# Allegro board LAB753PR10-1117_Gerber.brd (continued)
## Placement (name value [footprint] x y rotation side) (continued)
CV34  10U_0603_6.3V6M~D  [C_0603]  147.53 136.59 0 bottom
CV35  0.1U_0402_16V7K~D  [C_0402]  146.53 136.93 180 bottom
CV37  0.1U_0402_10V7K  [C_0402]  113.93 143.89 90 top
CV38  0.1U_0402_10V7K  [C_0402]  113.01 143.89 90 top
CV39  0.1U_0402_10V7K  [C_0402]  112.08 144.64 90 top
CV41  0.1U_0402_10V7K  [C_0402]  111.14 144.64 90 top
CV42  0.1U_0402_10V7K  [C_0402]  110.26 143.8 90 top
CV43  0.1U_0402_10V7K  [C_0402]  109.35 143.8 90 top
CV44  0.1U_0402_10V7K  [C_0402]  108.47 143.82 90 top
CV45  0.1U_0402_10V7K  [C_0402]  107.52 143.83 90 top
CV47  0.1U_0402_16V7K  [C_0402]  135.22 135.61 270 bottom
CV54  0.1U_0402_25V6K~D  [C_0402]  138.09 82.31 90 bottom
CV57  0.22U_0402_10V6K  [C_0402]  152.59 82.94 0 top
CV58  0.22U_0402_10V6K  [C_0402]  152.9 85.87 0 top
CV59  0.22U_0402_10V6K  [C_0402]  154.93 84.27 0 top
CV60  0.22U_0402_10V6K  [C_0402]  154.93 85.2 0 top
CV61  0.22U_0402_10V6K  [C_0402]  154.93 88.01 0 top
CV62  0.22U_0402_10V6K  [C_0402]  152.59 83.87 0 top
CV63  0.22U_0402_10V6K  [C_0402]  152.9 86.8 0 top
CV64  0.22U_0402_10V6K  [C_0402]  154.93 87.11 0 top
CV65  0.22U_0402_10V6K  [C_0402]  152.59 91.13 0 top
CV66  0.22U_0402_10V6K  [C_0402]  154.93 93.6 0 top
CV67  0.22U_0402_10V6K  [C_0402]  153.09 89.47 0 top
CV68  0.22U_0402_10V6K  [C_0402]  154.93 90.79 0 top
CV69  0.22U_0402_10V6K  [C_0402]  154.93 89.86 0 top
CV70  0.22U_0402_10V6K  [C_0402]  152.59 92.06 0 top
CV71  0.22U_0402_10V6K  [C_0402]  153.09 88.49 0 top
CV72  0.22U_0402_10V6K  [C_0402]  154.93 92.67 0 top
CV73  22P_0402_50V8J  [C_0402]  170.52 64.31 180 bottom
CV74  22P_0402_50V8J  [C_0402]  167.76 64.31 0 bottom
CV75  0.1U_0402_10V7K  [C_0402]  190.01 83.93 180 top
CV76  0.1U_0402_10V7K  [C_0402]  170.89 88.2 270 top
CV80  0.1U_0402_10V7K  [C_0402]  170.76 89.06 90 top
CV81  10U_0603_6.3V6M  [C_0603]  211.71 103.91 90 top
CV82  4.7U_0603_6.3V6K  [C_0603]  229.53 77.24 0 top
CV83  4.7U_0603_6.3V6K  [C_0603]  229.53 77.24 0 bottom
CV84  4.7U_0603_6.3V6K  [C_0603]  176.41 100.27 90 top
CV85  22U_0805_6.3V6M  [C_0805]  229.59 86.86 0 top
CV86  22U_0805_6.3V6M  [C_0805]  229.61 86.86 0 bottom
CV87  22U_0805_6.3V6M  [C_0805]  229.58 70.07 0 bottom
CV88  22U_0805_6.3V6M  [C_0805]  229.58 70.07 0 top
CV89  10U_0603_6.3V6M  [C_0603]  213.11 103.91 90 top
CV90  10U_0603_6.3V6M  [C_0603]  215.9 103.91 90 top
CV91  4.7U_0603_6.3V6K  [C_0603]  178.82 98.45 90 top
CV92  4.7U_0603_6.3V6K  [C_0603]  188.39 74.29 270 top
CV93  10U_0603_6.3V6M  [C_0603]  230.95 72.89 180 top
CV94  10U_0603_6.3V6M  [C_0603]  158.31 93.52 90 bottom
CV95  4.7U_0603_6.3V6K  [C_0603]  158.32 96.98 90 bottom
CV96  1U_0402_6.3V6K  [C_0402]  169.23 88.47 90 top
CV97  22U_0805_6.3V6M  [C_0805]  154.38 96.92 90 bottom
CV98  10U_0603_6.3V6M  [C_0603]  157.11 93.52 90 bottom
CV99  10U_0603_6.3V6M  [C_0603]  155.9 93.52 90 bottom
CV100  1U_0402_6.3V6K  [C_0402]  190.01 83.04 180 top
CV101  1U_0402_6.3V6K  [C_0402]  189.17 79.47 90 top
CV102  1U_0402_6.3V6K  [C_0402]  190.01 84.82 180 top
CV103  1U_0402_6.3V6K  [C_0402]  191.49 92.6 0 top
CV104  1U_0402_6.3V6K  [C_0402]  189.17 90.9 90 top
CV105  1U_0402_6.3V6K  [C_0402]  190.77 80.63 0 top
CV106  1U_0402_6.3V6K  [C_0402]  188.01 96.69 270 top
CV107  1U_0402_6.3V6K  [C_0402]  185.39 96.77 270 top
CV108  22U_0805_6.3V6M  [C_0805]  151.39 102.2 270 top
CV109  0.1U_0402_10V7K  [C_0402]  183.64 96.76 270 top
CV110  4.7U_0603_6.3V6K  [C_0603]  190.46 76.23 315 top
CV111  10U_0603_6.3V6M  [C_0603]  154.43 94.79 0 top
CV112  1U_0402_6.3V6K  [C_0402]  181.03 96.78 270 top
CV113  1U_0402_6.3V6K  [C_0402]  176.28 96.77 270 top
CV114  1U_0402_6.3V6K  [C_0402]  169.29 93.49 90 top
CV115  22U_0805_6.3V6M  [C_0805]  152.6 96.92 90 bottom
CV116  22U_0805_6.3V6M  [C_0805]  152.6 94.81 270 bottom
CV117  1U_0402_6.3V6K  [C_0402]  168.86 85.56 180 top
CV118  1U_0402_6.3V6K  [C_0402]  169.29 91.2 90 top
CV119  4.7U_0603_6.3V6K  [C_0603]  155.83 96.06 180 top
CV120  22U_0805_6.3V6M  [C_0805]  154.38 94.81 270 bottom
CV121  4.7U_0603_6.3V6K  [C_0603]  167.96 80.85 90 top
CV122  0.1U_0402_10V7K  [C_0402]  170.75 91.76 270 top
CV123  1U_0402_6.3V6K  [C_0402]  169.88 90.26 180 top
CV124  1U_0603_10V6K  [C_0603]  167.83 95.59 0 top
CV125  4.7U_0805_25V6-K  [C_0805]  156.15 96.92 90 bottom
CV126  0.1U_0402_10V7K  [C_0402]  170.02 87.25 270 top
CV127  0.1U_0402_10V7K  [C_0402]  169.5 79.28 0 top
CV128  0.1U_0402_10V7K  [C_0402]  169.29 78.23 0 top
CV129  1U_0603_10V6K  [C_0603]  168.76 76.76 0 top
CV130  4.7U_0805_25V6-K  [C_0805]  171.31 75.07 180 top
CV131  0.1U_0402_10V7K  [C_0402]  181.89 96.78 270 top
CV132  0.1U_0402_10V7K  [C_0402]  169.01 80.71 0 top
CV133  1U_0603_10V6K  [C_0603]  155.79 78.63 180 bottom
CV134  4.7U_0805_25V6-K  [C_0805]  155.92 80.16 180 bottom
CV135  1U_0402_6.3V6K  [C_0402]  189.17 76.81 90 top
CV136  1U_0402_6.3V6K  [C_0402]  174.13 99.05 90 top
CV137  22U_0805_6.3V6M  [C_0805]  191.54 86.16 0 top
CV138  22U_0805_6.3V6M  [C_0805]  190.13 95.11 90 top
CV139  10U_0603_6.3V6M  [C_0603]  230.89 88.76 180 top
CV140  10U_0603_6.3V6M  [C_0603]  210.31 103.91 90 top
CV141  1U_0402_6.3V6K  [C_0402]  182.77 96.78 270 top
CV142  1U_0402_6.3V6K  [C_0402]  185.31 77.64 180 top
CV143  4.7U_0603_6.3V6K  [C_0603]  186 75.04 270 top
CV144  4.7U_0603_6.3V6K  [C_0603]  183.62 97.84 90 top
CV145  4.7U_0603_6.3V6K  [C_0603]  214.51 105.31 270 top
CV146  4.7U_0603_6.3V6K  [C_0603]  229.49 88.76 0 bottom
CV147  0.1U_0402_10V7K  [C_0402]  180 76.76 90 top
CV148  22U_0805_6.3V6M  [C_0805]  156.73 64.99 90 bottom
CV149  0.1U_0402_10V7K  [C_0402]  171.35 76.85 0 top
CV150  10U_0603_6.3V6M  [C_0603]  180.31 91.05 0 top
CV151  10U_0603_6.3V6M  [C_0603]  180.3 83.44 0 top
CV152  10U_0603_6.3V6M  [C_0603]  180.19 81.49 0 top
CV153  0.1U_0402_10V6K  [C_0402]  162.45 119.68 180 bottom
CV154  0.1U_0402_10V6K  [C_0402]  161.71 132.91 180 top
CV155  0.1U_0402_10V6K  [C_0402]  184.03 130.63 90 bottom
CV156  0.1U_0402_10V6K  [C_0402]  180.47 126.65 90 top
CV157  10U_0603_6.3V6M  [C_0603]  175.65 84.18 180 top
CV158  10U_0603_6.3V6M  [C_0603]  176.49 81.24 0 top
CV159  4.7U_0603_6.3V6K  [C_0603]  187.52 93.44 270 top
CV160  0.1U_0402_10V6K  [C_0402]  162.46 118.8 180 bottom
CV161  0.1U_0402_10V6K  [C_0402]  179.59 124.81 90 bottom
CV162  1U_0402_6.3V4Z  [C_0402]  179.59 115.5 270 bottom
CV163  1U_0402_6.3V4Z  [C_0402]  179.59 117.28 270 bottom
CV164  0.1U_0402_10V6K  [C_0402]  162.46 117.92 180 bottom
CV165  0.1U_0402_10V6K  [C_0402]  179.59 126.65 90 bottom
CV166  1U_0402_6.3V4Z  [C_0402]  162.45 123.23 180 bottom
CV167  0.1U_0402_10V6K  [C_0402]  165.69 129.69 90 top
CV168  0.1U_0402_10V6K  [C_0402]  162.32 124.36 180 top
CV169  1U_0402_6.3V4Z  [C_0402]  166.58 131.49 180 top
CV170  1U_0402_6.3V4Z  [C_0402]  162.32 123.48 180 top
CV171  0.1U_0402_10V6K  [C_0402]  176.72 130.7 90 top
CV172  0.1U_0402_10V6K  [C_0402]  175.83 130.7 90 top
CV173  1U_0402_6.3V4Z  [C_0402]  179.59 124.81 90 top
CV174  0.1U_0402_10V6K  [C_0402]  180.47 115.5 270 bottom
CV175  0.1U_0402_10V6K  [C_0402]  180.47 117.28 270 bottom
CV178  820P_0402_25V7  [C_0402]  229.53 95.51 270 top
CV179  820P_0402_25V7  [C_0402]  215.13 103.98 0 bottom
CV180  0.1U_0402_10V6K  [C_0402]  215.71 65.79 270 top
CV181  0.1U_0402_10V6K  [C_0402]  224.87 84.16 180 top
CV182  1U_0402_6.3V4Z  [C_0402]  227.52 83.3 0 top
CV184  0.1U_0402_10V6K  [C_0402]  222 66.16 270 top
CV185  0.1U_0402_10V6K  [C_0402]  229.73 80.65 0 top
CV186  1U_0402_6.3V4Z  [C_0402]  214.11 83.28 0 top
CV187  1U_0402_6.3V4Z  [C_0402]  226.65 83.3 180 top
CV188  0.1U_0402_10V6K  [C_0402]  222.96 66.23 270 bottom
CV189  0.1U_0402_10V6K  [C_0402]  229.73 79.63 0 top
CV190  1U_0402_6.3V4Z  [C_0402]  229.73 78.62 0 top
CV191  1U_0402_6.3V4Z  [C_0402]  229.73 80.65 0 bottom
CV192  0.1U_0402_10V6K  [C_0402]  229.35 84.15 0 bottom
CV193  0.1U_0402_10V6K  [C_0402]  229.73 79.63 0 bottom
CV194  1U_0402_6.3V4Z  [C_0402]  229.73 78.62 0 bottom
CV195  0.1U_0402_16V4Z~D  [C_0402]  153.09 80.61 270 bottom
CV198  1U_0402_6.3V4Z  [C_0402]  180.47 122.87 270 bottom
CV199  1U_0402_6.3V4Z  [C_0402]  180.47 124.81 90 bottom
CV200  0.1U_0402_10V6K  [C_0402]  163.45 128.49 90 bottom
CV201  0.1U_0402_10V6K  [C_0402]  179.59 126.65 90 top
CV202  0.1U_0402_10V6K  [C_0402]  180.47 126.65 90 bottom
CV203  0.1U_0402_10V7K  [C_0402]  190.69 90.34 0 top
CV204  0.1U_0402_10V7K  [C_0402]  190.08 78.57 180 top
CV205  0.1U_0402_10V7K  [C_0402]  189.17 81.25 90 top
CV206  0.1U_0402_10V7K  [C_0402]  189.17 90.04 270 top
CV207  0.1U_0402_10V7K  [C_0402]  190.01 85.71 180 top
CV208  0.1U_0402_10V7K  [C_0402]  173.3 96.77 270 top
CV209  0.1U_0402_10V7K  [C_0402]  186.19 76.74 90 top
CV210  0.1U_0402_10V6K  [C_0402]  197.61 114.16 0 bottom
CV211  0.1U_0402_10V6K  [C_0402]  197.61 115.11 0 bottom
CV212  0.1U_0402_10V7K  [C_0402]  153.74 73.5 90 bottom
CV213  1U_0402_6.3V4Z  [C_0402]  197.61 116.06 0 bottom
CV214  0.1U_0402_10V6K  [C_0402]  184.13 130.64 90 top
CV215  0.1U_0402_10V7K  [C_0402]  187.07 77.64 0 top
CV216  0.1U_0402_10V6K  [C_0402]  162.46 116.14 180 bottom
CV217  10U_0603_6.3V6M  [C_0603]  178.22 129.95 90 bottom
CV218  10U_0603_6.3V6M  [C_0603]  162.97 124.32 180 bottom
CV219  0.1U_0402_10V6K  [C_0402]  162.45 122.33 180 bottom
CV220  1U_0402_6.3V4Z  [C_0402]  162.46 117.03 180 bottom
CV221  0.1U_0402_10V6K  [C_0402]  171.62 130.61 90 bottom
CV222  0.1U_0402_10V6K  [C_0402]  164.73 129.68 0 bottom
CV223  0.1U_0402_10V6K  [C_0402]  174.51 130.7 90 top
CV224  10U_0603_6.3V6M  [C_0603]  180.57 130.04 90 top
CV225  10U_0603_6.3V6M  [C_0603]  173.23 130.57 90 top
CV226  0.1U_0402_10V6K  [C_0402]  179.63 113.69 0 top
CV227  1U_0402_6.3V4Z  [C_0402]  179.59 117.28 270 top
CV228  0.1U_0402_10V6K  [C_0402]  179.59 115.5 270 top
CV229  0.1U_0402_10V6K  [C_0402]  163.5 128.11 180 top
CV230  0.1U_0402_10V6K  [C_0402]  190.69 130.63 90 bottom
CV231  10U_0603_6.3V6M  [C_0603]  197.68 127.05 0 bottom
CV232  10U_0603_6.3V6M  [C_0603]  197.68 128.32 0 bottom
CV233  0.1U_0402_10V6K  [C_0402]  189.8 130.63 90 bottom
CV234  1U_0402_6.3V4Z  [C_0402]  197.61 124.19 0 bottom
CV235  0.1U_0402_10V6K  [C_0402]  197.61 125.97 0 bottom
CV236  0.1U_0402_10V6K  [C_0402]  197.61 125.08 0 bottom
CV237  0.1U_0402_10V6K  [C_0402]  179.47 130.7 90 top
CV238  10U_0603_6.3V6M  [C_0603]  195.37 130.72 90 top
CV239  10U_0603_6.3V6M  [C_0603]  196.6 130.71 90 top
CV240  0.1U_0402_10V6K  [C_0402]  182.35 130.64 90 top
CV241  0.1U_0402_10V6K  [C_0402]  183.23 130.64 90 top
CV242  1U_0402_6.3V4Z  [C_0402]  201.6 128.12 0 top
CV243  1U_0402_6.3V4Z  [C_0402]  185.17 130.63 90 top
CV244  0.1U_0402_10V6K  [C_0402]  178.55 130.7 90 top
CV245  0.1U_0402_10V6K  [C_0402]  177.66 130.7 90 top
CV246  0.1U_0402_10V6K  [C_0402]  180.47 115.5 270 top
CV247  1U_0402_6.3V4Z  [C_0402]  180.47 117.28 270 top
CV248  1U_0402_6.3V4Z  [C_0402]  180.47 124.81 90 top
CV249  0.1U_0402_10V6K  [C_0402]  186.12 130.63 90 top
CV250  0.1U_0402_10V6K  [C_0402]  180.47 122.6 270 top
CV252  0.1U_0402_10V6K  [C_0402]  227.52 84.18 0 top
CV253  10U_0603_6.3V6M  [C_0603]  228.29 101.46 90 top
CV254  0.1U_0402_10V6K  [C_0402]  226.65 84.18 180 top
CV255  0.1U_0402_10V6K  [C_0402]  213.24 83.33 90 top
CV256  0.1U_0402_10V6K  [C_0402]  224.8 101.44 90 top
CV257  10U_0603_6.3V6M  [C_0603]  226.96 101.46 90 top
CV258  1U_0402_6.3V4Z  [C_0402]  225.69 101.44 90 top
CV259  1U_0402_6.3V4Z  [C_0402]  229.55 99.1 270 top
CV260  0.1U_0402_10V6K  [C_0402]  223.91 101.44 90 top
CV261  0.1U_0402_10V6K  [C_0402]  223.02 101.44 90 top
CV262  0.1U_0402_10V6K  [C_0402]  222.13 101.44 90 top
CV263  1U_0402_6.3V4Z  [C_0402]  221.18 101.44 90 top
CV264  1U_0402_6.3V4Z  [C_0402]  214.7 101.63 90 top
CV265  0.1U_0402_10V6K  [C_0402]  217.5 101.63 90 top
CV266  0.1U_0402_10V6K  [C_0402]  216.54 101.63 90 top
CV267  0.1U_0402_10V6K  [C_0402]  223.96 84.18 0 bottom
CV268  10U_0603_6.3V6M  [C_0603]  222.95 83.47 180 bottom
CV269  10U_0603_6.3V6M  [C_0603]  229.49 90.05 0 bottom
CV270  0.1U_0402_10V6K  [C_0402]  226.65 84.18 180 bottom
CV271  0.1U_0402_10V6K  [C_0402]  227.52 84.18 0 bottom
CV272  0.1U_0402_10V6K  [C_0402]  214.12 83.28 0 bottom
CV273  0.1U_0402_10V6K  [C_0402]  224.8 101.44 90 bottom
CV274  1U_0402_6.3V4Z  [C_0402]  214.12 84.18 0 bottom
CV275  1U_0402_6.3V4Z  [C_0402]  229.56 99.09 270 bottom
CV276  0.1U_0402_10V6K  [C_0402]  229.56 100.87 270 bottom
CV277  0.1U_0402_10V6K  [C_0402]  225.69 101.44 90 bottom
CV278  0.1U_0402_10V6K  [C_0402]  211.08 101.6 90 bottom
CV279  1U_0402_6.3V4Z  [C_0402]  212.03 101.6 90 bottom
CV280  1U_0402_6.3V4Z  [C_0402]  223.91 101.44 90 bottom
CV281  0.1U_0402_10V6K  [C_0402]  226.57 101.42 90 bottom
CV282  0.1U_0402_10V6K  [C_0402]  210.19 101.61 90 bottom
CV283  0.1U_0402_10V6K  [C_0402]  215.59 101.63 90 top
CV284  0.1U_0402_10V6K  [C_0402]  229.91 68.38 0 top
CV285  10U_0603_6.3V6M  [C_0603]  229.55 72.89 0 bottom
CV286  10U_0603_6.3V6M  [C_0603]  229.55 74.44 0 top
CV287  0.1U_0402_10V6K  [C_0402]  222.96 66.16 270 top
CV288  1U_0402_6.3V4Z  [C_0402]  214.61 65.8 270 top
CV289  0.1U_0402_10V6K  [C_0402]  229.91 67.36 0 top
CV290  0.1U_0402_10V6K  [C_0402]  215.89 83.3 0 top
CV291  0.1U_0402_10V6K  [C_0402]  217.43 65.87 270 top
CV292  10U_0603_6.3V6M  [C_0603]  229.53 75.81 0 top
CV293  10U_0603_6.3V6M  [C_0603]  229.55 71.59 0 top
CV294  0.1U_0402_10V6K  [C_0402]  227.52 83.3 0 bottom
CV295  0.1U_0402_10V6K  [C_0402]  223.96 83.3 0 bottom
CV296  1U_0402_6.3V4Z  [C_0402]  226.65 83.3 180 bottom
CV297  0.1U_0402_10V6K  [C_0402]  215.89 83.3 0 bottom
CV298  0.1U_0402_10V6K  [C_0402]  222 66.23 270 bottom
CV299  820P_0402_25V7  [C_0402]  229.53 95.5 270 bottom
CV300  820P_0402_25V7  [C_0402]  216.53 101.61 0 bottom
CV301  820P_0402_25V7  [C_0402]  179.58 122.85 270 bottom
CV302  820P_0402_25V7  [C_0402]  169.41 130.6 0 top
CV303  820P_0402_25V7  [C_0402]  161.56 121.46 270 bottom
CV304  820P_0402_25V7  [C_0402]  173.03 130.6 0 bottom
CV305  820P_0402_25V7  [C_0402]  197.68 127.67 90 top
CV306  820P_0402_25V7  [C_0402]  192.55 130.69 180 bottom
CV307  820P_0402_25V7  [C_0402]  197.61 123.24 0 bottom
CV308  820P_0402_25V7  [C_0402]  192.55 130.68 180 top
CV309  820P_0402_25V7  [C_0402]  219.07 66.21 0 bottom
CV310  820P_0402_25V7  [C_0402]  219.07 64.44 0 bottom
CV311  820P_0402_25V7  [C_0402]  220.1 66.16 270 top
CV312  820P_0402_25V7  [C_0402]  229.47 75.97 0 bottom
CV313  0.1U_0402_10V6K  [C_0402]  229.91 68.38 0 bottom
CV314  0.1U_0402_10V6K  [C_0402]  229.91 67.36 0 bottom
CV315  0.1U_0402_10V6K  [C_0402]  214.11 84.16 0 top
CV317  4.7U_0603_6.3V6K  [C_0603]  177.48 93.18 90 top
CV318  4.7U_0603_6.3V6K  [C_0603]  178.7 86.24 180 top
CV319  4.7U_0603_6.3V6K  [C_0603]  172.49 90.39 270 top
CV320  4.7U_0603_6.3V6K  [C_0603]  187.52 87.53 270 top
CV321  4.7U_0603_6.3V6K  [C_0603]  183.44 89.37 270 top
CV322  4.7U_0603_6.3V6K  [C_0603]  184.67 86.31 180 top
CV323  4.7U_0603_6.3V6K  [C_0603]  172.49 80.04 90 top
CV324  4.7U_0603_6.3V6K  [C_0603]  187.52 89.12 90 top
CV325  4.7U_0603_6.3V6K  [C_0603]  170.75 82.01 180 top
CV326  4.7U_0603_6.3V6K  [C_0603]  181.69 85.16 180 top
CV327  4.7U_0603_6.3V6K  [C_0603]  178.76 88.15 180 top
CV328  4.7U_0603_6.3V6K  [C_0603]  187.52 83.02 90 top
CV329  4.7U_0603_6.3V6K  [C_0603]  179.54 68.12 270 top
CV330  4.7U_0603_6.3V6K  [C_0603]  181.69 87.26 180 top
CV331  4.7U_0603_6.3V6K  [C_0603]  172.49 84.49 270 top
CV332  4.7U_0603_6.3V6K  [C_0603]  187.52 81.37 270 top
CV333  4.7U_0603_6.3V6K  [C_0603]  171.41 71.07 180 top
CV334  4.7U_0603_6.3V6K  [C_0603]  181.71 89.24 180 top
CV335  4.7U_0603_6.3V6K  [C_0603]  172.49 86.08 90 top
CV338  47U_0805_6.3V6M~D  [C_0805]  229.62 82.18 0 bottom
CV339  47U_0805_6.3V6M~D  [C_0805]  229.62 82.18 0 top
CV364  0.1U_0402_16V7K  [C_0402]  177.17 96.77 270 top
CV365  0.1U_0402_16V7K  [C_0402]  190.01 87.74 180 top
CV366  0.1U_0402_16V7K  [C_0402]  190.01 86.79 180 top
CV367  0.1U_0402_16V7K  [C_0402]  183.01 76.81 90 top
CV368  220P_0402_50V8J  [C_0402]  153.38 60.94 90 top
CV369  220P_0402_50V8J  [C_0402]  154.27 60.95 90 top
CV372  10P_0402_50V8J  [C_0402]  80.84 117.09 315 bottom
CV373  10P_0402_50V8J  [C_0402]  88.46 120.5 270 bottom
CV374  10P_0402_50V8J  [C_0402]  83.49 125.19 0 bottom
CV375  10P_0402_50V8J  [C_0402]  82.59 119.95 180 top
CV376  10P_0402_50V8J  [C_0402]  155.75 147.54 0 bottom
CV377  10P_0402_50V8J  [C_0402]  147.69 137.7 0 bottom
CV379  0.1U_0402_10V7K  [C_0402]  178.4 80.15 0 top
CV380  0.1U_0402_10V7K  [C_0402]  176.42 92.17 180 top
CV394  0.1U_0402_10V7K  [C_0402]  171.35 77.73 0 top
CV396  0.1U_0402_10V7K  [C_0402]  184.52 96.76 270 top
CV397  10U_0603_6.3V6M  [C_0603]  151.75 97.18 0 top
CV398  47U_0805_6.3V6M~D  [C_0805]  153.33 98.71 180 top
CV408  100P_0402_50V8J~D  [C_0402]  159.67 40.86 0 top
CV409  10U_0603_6.3V6M  [C_0603]  160.4 33.81 270 top
CV410  10U_0603_6.3V6M  [C_0603]  164.47 36.67 90 top
CV411  4.7U_0603_6.3V6K  [C_0603]  182.12 52.28 0 top
CV412  4.7U_0603_6.3V6K  [C_0603]  186.72 52.3 180 top
CV413  4.7U_0603_6.3V6K  [C_0603]  179.87 50.57 180 top
CV414  4.7U_0603_6.3V6K  [C_0603]  179.87 52.29 180 top
CV415  4.7U_0603_6.3V6K  [C_0603]  182.12 50.56 0 top
CV422  0.1U_0402_10V7K  [C_0402]  112.78 141.9 180 bottom
CV423  0.1U_0402_10V7K  [C_0402]  107.47 138.39 0 bottom
CV424  0.01U_0402_16V7K  [C_0402]  105.32 141.66 90 bottom
CV425  0.01U_0402_16V7K  [C_0402]  106.2 141.66 90 bottom
CV426  0.01U_0402_16V7K  [C_0402]  107.47 139.27 0 bottom
CV427  0.01U_0402_16V7K  [C_0402]  105.32 141.66 90 top
CV428  0.01U_0402_16V7K  [C_0402]  106.2 141.66 90 top
CV429  0.1U_0402_10V7K  [C_0402]  112.79 141.01 180 bottom
CV1025  330U_D2_2V_Y  [C_D2]  174.28 73.7 270 top
CZ6  2200P_0402_50V7K  [C_0402]  240.68 34.2 180 bottom
DA15  -  [BAT54AW_SOT323-3]  2.64 15.1 0 bottom
DE1  SDMK0340L-7-F_SOD323-2~D  [SDMK0340L-7-F_SOD323-2]  274.04 20.93 135 bottom
DE2  -  [L03ESDL5V0CG3-2_SOT-523-3]  295.14 22.15 180 top
DE3  SDMK0340L-7-F_SOD323-2~D  [SDMK0340L-7-F_SOD323-2]  7.36 12.05 90 bottom
DF1  -  [SDMK0340L-7-F_SOD323-2]  67.53 63.32 270 bottom
DF2  -  [SDMK0340L-7-F_SOD323-2]  247.48 45.72 315 bottom
DH1  -  [RB751V-40_SOD323-2]  241.74 17.68 180 top
DI2  -  [L30ESDL5V0C3-2_SOT23-3]  322.07 59.82 180 bottom
DI3  -  [TVWDF1004AD0_DFN9]  323.46 65.99 270 bottom
DI4  -  [L30ESDL5V0C3-2_SOT23-3]  322.07 48.57 0 bottom
DI5  -  [TVWDF1004AD0_DFN9]  323.53 52.65 270 bottom
DN1  SDM10U45-7_SOD523-2~D  [SDM10U45-7_SOD523-2]  153.28 15.74 0 bottom
DU8  -  [SDMK0340L-7-F_SOD323-2]  17.27 38.44 180 bottom
DU9  -  [SDMK0340L-7-F_SOD323-2]  16.79 34.32 180 top
DV1  -  [RB751V-40_SOD323-2]  89.31 118.07 315 top
DV2  -  [PESD5V0U2BT_SOT23-3]  92.76 120.48 315 top
DV4  -  [DAN202UT106_SC70-3]  143.21 81.42 90 bottom
DV8  -  [BAT54A-7-F_SOT23-3]  152.73 58.71 0 bottom
DV9  -  [RB751S40T1G_SOD523-2]  156.34 64.76 180 top
FD1  FIDUCAL  [FIDUCIAL_C40M80]  322.68 91.72 0 top
FD2  FIDUCIAL  [FIDUCIAL_C40M80]  46.46 10.44 180 bottom
FD3  FIDUCAL  [FIDUCIAL_C40M80]  55.42 46.59 0 top
FD4  FIDUCIAL  [FIDUCIAL_C40M80]  322.2 109.31 180 bottom
H1  -  [H_3P5X4P1]  331.5 115.28 0 top
H2  -  [H_3P5X4P1]  201.5 138.93 90 top
H3  -  [H_2P8]  337.5 115.28 0 top
H4  -  [H_2P8]  3.5 38.78 0 top
H5  -  [H_2P8]  86.1 58.21 0 top
H6  -  [H_2P8]  238.5 58.49 0 top
H8  -  [H_2P8]  147.9 7.28 0 top
H9  -  [H_2P8]  65.8 8.78 0 top
H10  -  [H_2P8]  102.5 146.78 0 top
H11  -  [H_2P8]  201.5 144.93 0 top
H12  -  [H_2P8]  147.92 65.22 0 top
H13  -  [H_2P8]  326.69 3.48 0 top
H14  -  [H_2P8]  256.35 8.78 0 top
H15  -  [H_3P5]  331.54 7.01 0 top
H16  -  [H_3P8]  203.32 121.74 0 top
H17  -  [H_3P8]  154.32 121.74 0 top
H18  -  [H_3P8]  140.55 102.38 0 top
H19  -  [H_3P8]  140.55 70.38 0 top
H20  -  [H_3P8]  82.15 100.36 0 top
H21  -  [H_3P8]  82.15 72.36 0 top
H22  -  [H_3P8]  203.82 59.74 0 top
H23  -  [H_3P8]  161.82 59.74 0 top
H24  -  [H_3P2]  199.85 26.78 0 top
H25  -  [H_2P0N]  88.5 90.86 0 top
H26  -  [H_2P0X2P3N]  82.15 94.36 0 top
J2  -  [JUMP_43X118]  249.6 39.14 180 top
J4  -  [JUMP_43X79]  58.65 16.22 180 top
J5  -  [JUMP_43X79]  58.65 10.25 180 top
J6  -  [JUMP_43X79]  219.59 16.58 270 top
JCDRA  TE_2260531-1  [TE_2260531-1_46P-T]  169.95 143.18 0 bottom
JCR  T-SOL_143-2300302602_RV  [T-SOL_143-2300302602_22P_RV]  302.17 33.54 270 bottom
JDIMM1  LCN_DAN06-K4406-0103  [FOX_AS0A621-H2R6-7H_204P]  78.65 38.78 180 bottom
JDIMM2  LCN_DAN06-K4806-0103  [FOX_AS0A621-HARN-7H_204P]  78.65 25.78 180 bottom
JDP1  FOX_3V111T1-R240KKA-7H  [FOX_3V111T1-R240KKA-7H_20P-T]  139.8 143.08 0 bottom
JEDP1  ACES_50473-0400M-P01  [ACES_50473-0400M-002_40P-T]  103.26 135.69 225 top
JELC1  AMPHE_G846A06201EU  [AMPHE_G846A06201EU_6P-T]  179.55 18.44 0 bottom
JFAN1  ACES_50273-00401-001  [ACES_50273-00401-001_4P]  60.72 54.21 225 bottom
JFAN2  ACES_50273-00401-001  [ACES_50273-00401-001_4P]  241.94 49.14 222.5 bottom
JHDD1  STARC_111H20-100000-G2-R  [STARC_111H20-100000-G2-R_20P]  161.95 31.53 270 bottom
JHDMI1  FUTUR_061-HA18-0001  [FUTUR_061-HA18-0001_19P-T]  119.5 140.38 0 bottom
JIO  I-PEX_20455-040E-12  [I-PEX_20455-040E-12_40P]  11.32 33.03 270 top
JKB1  ACES_50552-03001-001  [ACES_50552-03001-001_30P-T]  111.35 11.58 180 bottom
JKB2  -  [ACES_50611-0100N-001_10P]  78 12.95 0 bottom
JKB3  ACES_87153-06411  [ACES_87153-06411_6P]  56.65 9.03 180 bottom
JKBBL1  ACES_50552-02001-001  [ACES_50552-02001-001_20P-T]  137.25 11.58 180 bottom
JLAN  SANTA_130456-511  [SANTA_130456-511_13P-T]  328.98 104.65 270 bottom
JLOGO1  -  [ACES_50208-01201-P01_12P]  223.9 123.28 180 top
JP1  PAD-OPEN 4x4m  [JUMP_43X118]  108.58 50.53 270 top
JP2  PAD-OPEN 4x4m  [JUMP_43X118]  113.85 50.53 270 top
JPWR1  STARC_107K30-000001-G2  [STARC_107K30-000001-G2_30P]  173.15 147.98 0 top
JRTC1  ACES_50271-00201-001  [ACES_50271-00201-001_2P]  262.7 10.4 270 bottom
JSPK  ACES_50278-00401-001  [ACES_50278-00401-001_4P]  38.25 11.8 90 top
JSSD1  FOX_AS0BC21-S85BB-7H  [FOX_AS0BC21-S85BB-7H_67P-T]  246.15 12.97 180 bottom
JSSD2  FOX_AS0BC21-S85BB-7H  [FOX_AS0BC21-S85BB-7H_67P-T]  222.65 12.97 180 bottom
JSSD3  FOX_AS0BC21-S85BB-7H  [FOX_AS0BC21-S85BB-7H_67P-T]  196.65 12.97 180 bottom
JSSD4  FOX_AS0BC21-S85BB-7H  [FOX_AS0BC21-S85BB-7H_67P-T]  173.15 12.97 180 bottom
JTRONF  ACES_50208-01201-P01  [ACES_50208-01201-P01_12P]  183.01 14.08 0 top
JUSB1  JESSL_TNBNRAC70013009  [JESSL_TNBNRAC70013009_9P-T]  326.72 64.9 270 bottom
JUSB2  JESSL_TNBNRAC70013009  [JESSL_TNBNRAC70013009_9P-T]  326.72 46.6 270 bottom
JWLAN1  LOTES_APCI0019-P009A  [LOTES_APCI0019-P009A_67P]  166.33 36.03 270 bottom
LA2  BLM15BB221SN1D_2P  [MURAT_BLM15BB221SN1D_2P]  25.33 20.83 0 top
LA3  NBQ160808T-800Y-N 0603  [R_0603]  31.71 10.49 0 top
LA4  NBQ160808T-800Y-N 0603  [R_0603]  31.73 12.38 0 top
LA5  NBQ160808T-800Y-N 0603  [R_0603]  31.73 13.73 0 top
LA6  NBQ160808T-800Y-N 0603  [R_0603]  31.73 15.8 0 top
LA7  TAI-TECH HCB1608KF-121T30 0603  [R_0603]  8.87 17.88 180 bottom
LA9  BLM15AG121SN1D_L0402_2P  [MURAT_BLM15AG121SN1D_L0402_2P]  19.18 22.99 270 top
LA10  BLM15AG121SN1D_L0402_2P  [MURAT_BLM15AG121SN1D_L0402_2P]  15.99 15.56 90 bottom
LE1  FBMA-L11-160808-800LMT_0603  [KC_FBMA-L11-160808-800LMT_2P]  276.61 7.21 90 top
LE2  FBMA-L11-160808-800LMT_0603  [KC_FBMA-L11-160808-800LMT_2P]  278.16 7.21 90 top
LH1  4.7UH_LQM18FN4R7M00D_20%~D  [MURAT_LQM18FN4R7M00D_2P]  217.19 57.75 180 top
LI1  DLW21SN900SQ2L_0805_4P~D  [MURAT_DLW21SN900SQ2L_0805_4P]  317.6 60.46 0 bottom
LI2  DLW21SN900HQ2L_0805_4P~D  [MURAT_DLW21SN900HQ2L_0805_4P]  320.89 65.58 180 bottom
LI3  DLW21SN900HQ2L_0805_4P~D  [MURAT_DLW21SN900HQ2L_0805_4P]  320.89 63.67 180 bottom
LI4  DLW21SN900HQ2L_0805_4P~D  [MURAT_DLW21SN900HQ2L_0805_4P]  317.48 46.93 0 bottom
LI5  DLW21SN900HQ2L_0805_4P~D  [MURAT_DLW21SN900HQ2L_0805_4P]  320.96 50.28 180 bottom
LI6  DLW21SN900HQ2L_0805_4P~D  [MURAT_DLW21SN900HQ2L_0805_4P]  320.96 52.18 180 bottom
LI7  DLW21SN900SQ2L_0805_4P~D  [MURAT_DLW21SN900SQ2L_0805_4P]  15.93 21.15 180 top
LI8  DLW21SN900HQ2L_0805_4P~D  [MURAT_DLW21SN900HQ2L_0805_4P]  14.23 22.4 0 top
LI9  DLW21SN900HQ2L_0805_4P~D  [MURAT_DLW21SN900HQ2L_0805_4P]  14.23 24.49 0 top
LI10  DLW21SN900SQ2L_0805_4P~D  [MURAT_DLW21SN900SQ2L_0805_4P]  15.93 27.44 180 top
LI11  DLW21SN900HQ2L_0805_4P~D  [MURAT_DLW21SN900HQ2L_0805_4P]  14.23 28.69 0 top
LI12  DLW21SN900HQ2L_0805_4P~D  [MURAT_DLW21SN900HQ2L_0805_4P]  14.23 30.78 0 top
LI13  DLW21SN900HQ2L_0805_4P  [MURAT_DLW21SN900HQ2L_0805_4P]  186.23 136.63 270 bottom
LI14  DLW21SN900HQ2L_0805_4P  [MURAT_DLW21SN900HQ2L_0805_4P]  188.7 139.94 270 bottom
LL1  BLM15AG121SN1D_L0402_2P  [MURAT_BLM15AG121SN1D_L0402_2P]  325.82 73.58 90 top
LM1  WCM-2012HS-900T_4P  [KC_WCM-2012HS-900T_4P]  186.97 138.75 90 bottom
LM2  DLW21SN670HQ2L_4P  [MURAT_DLW21SN670HQ2L_4P]  163.93 38.46 270 bottom
LR1  MMZ1608R301AT_2P~D  [TDK_MMZ1608R301AT_2P]  333.85 16.62 90 top
LV2  WCM-2012HS-900T_4P  [KC_WCM-2012HS-900T_4P]  98.35 124.39 135 top
LV3  WCM-2012HS-900T_4P  [KC_WCM-2012HS-900T_4P]  122.44 134 45 bottom
LV4  WCM-2012HS-900T_4P  [KC_WCM-2012HS-900T_4P]  125.76 134.07 45 bottom
LV5  WCM-2012HS-900T_4P  [KC_WCM-2012HS-900T_4P]  119.46 134.23 45 bottom
LV6  WCM-2012HS-900T_4P  [KC_WCM-2012HS-900T_4P]  116.32 134.41 45 bottom
LV8  FBMA-L11-201209-221LMA30T_0805  [KC_FBMA-L11-201209-221LMA30_2P]  85.04 123 315 bottom
LV9  BLM18KG300TN1D_2P  [CHILI_PBY160808T-300Y-N_2P]  153.13 101.76 270 top
LV14  PBY160808T-300Y-N_2P  [CHILI_PBY160808T-300Y-N_2P]  157.64 63.67 180 bottom
LV15  PBY160808T-301Y-N  [CHILI_PBY160808T-300Y-N_2P]  154.52 97.41 0 top
NOREF  -  []  125.87 49.86 0 top
NOREF#2  -  []  203.32 121.74 0 top
NOREF#3  -  []  117.1 42.71 0 top
NOREF#4  -  []  161.82 59.74 0 top
NOREF#5  -  []  93.46 9.49 0 top
NOREF#6  -  []  133.68 -14.12 0 top
NOREF#7  -  []  238.5 58.49 0 top
NOREF#8  -  []  82.15 100.36 0 top
NOREF#9  -  []  256.35 8.78 180 top
NOREF#10  -  []  154.32 121.74 0 top
NOREF#11  -  []  201.5 144.43 0 top
NOREF#12  -  []  3.5 38.78 0 top
NOREF#13  -  []  161.82 59.74 0 top
NOREF#14  -  []  203.82 59.74 0 top
NOREF#15  -  []  203.32 121.74 0 top
NOREF#16  -  []  147.92 65.22 0 top
NOREF#17  -  []  215.36 -31.98 0 top
NOREF#18  -  []  86.1 58.21 0 top
NOREF#19  -  []  154.32 121.74 0 top
NOREF#20  -  []  102.5 146.78 0 top
NOREF#21  -  []  140.55 70.38 0 top
NOREF#22  -  []  65.8 8.78 180 top
NOREF#23  -  []  82.15 72.36 0 top
NOREF#24  -  []  86.9 230.13 0 top
NOREF#25  -  []  199.85 26.78 0 top
NOREF#26  -  []  79.53 30.29 0 top
NOREF#27  -  []  140.55 102.38 0 top
NOREF#28  -  []  203.82 59.74 0 top
NOREF#29  -  []  291.78 102.94 180 bottom
NOREF#30  -  []  135.64 74.61 90 bottom
NOREF#31  -  []  205.88 68.96 90 bottom
PBATT1  ACES_51481-01371-P01  [ACES_51481-01371-P01_13P]  66 34.78 270 bottom
PC1  1000P_0402_50V7K  [C_0402]  50.93 18.84 270 bottom
PC2  100P_0402_50V8J  [C_0402]  50.04 18.84 270 bottom
PC3  1000P_0402_50V7K  [C_0402]  45.68 18.89 270 bottom
PC4  100P_0402_50V8J  [C_0402]  46.57 18.89 270 bottom
PC6  0.022U_0402_25V7K  [C_0402]  68.07 47.51 90 bottom
PC7  0.01U_0402_25V7K  [C_0402]  67.12 47.51 90 bottom
PC8  1000P_0402_50V7K  [C_0402]  64.49 37.44 90 top
PC9  100P_0402_50V8J  [C_0402]  65.35 37.44 90 top
PC10  0.22U_0603_25V7K  [C_0603]  64.75 18.02 0 top
PC11  0.1U_0402_25V6  [C_0402]  63.41 15.13 270 top
PC12  .1U_0402_16V7K  [C_0402]  69.93 14.98 0 top
PC13  .1U_0402_16V7K  [C_0402]  294.15 13.06 90 top
PC14  1U_0603_25V6K  [C_0603]  73.6 28.32 270 top
PC15  0.1U_0402_25V6  [C_0402]  143.26 57.99 90 bottom
PC16  0.1U_0402_25V6  [C_0402]  83.11 47.96 270 bottom
PC100  0.1U_0402_25V6  [C_0402]  36.53 29.75 180 top
PC101  4.7U_0603_6.3V6K  [C_0603]  20.53 28.88 180 top
PC102  10U_0805_25V6K  [C_0805]  38.7 32.48 180 bottom
PC103  2200P_0402_50V7K  [C_0402]  36.53 27.78 180 top
PC104  10U_0805_25V6K  [C_0805]  38.51 25.62 180 bottom
PC105  0.1U_0402_25V6  [C_0402]  23.56 25.12 270 top
PC106  0.1U_0402_25V6  [C_0402]  23.31 33.57 270 top
PC107  220U_6.3V_M  [C_APXK6R3ARA221MF451]  22.54 20.87 90 bottom
PC108  220U_6.3V_M  [C_APXK6R3ARA221MF451]  24.82 35.59 180 bottom
PC109  680P_0603_50V8J  [C_0603]  36.13 20.6 90 top
PC110  680P_0603_50V8J  [C_0603]  27.94 32.09 270 top
PC111  4.7U_0603_6.3V6K  [C_0603]  26.74 30.72 90 top
PC112  4.7U_0603_6.3V6K  [C_0603]  23.12 36.54 180 top
PC113  10U_0805_25V6K  [C_0805]  38.51 23.84 180 bottom
PC114  10U_0805_25V6K  [C_0805]  38.7 34.25 180 bottom
PC200  0.1U_0402_25V6  [C_0402]  148.64 41.05 0 top
PC201  2200P_0402_50V7K  [C_0402]  148.64 41.94 0 top
PC202  10U_0805_25V6K  [C_0805]  152.69 43.72 270 top
PC203  10U_0805_25V6K  [C_0805]  150.89 43.72 270 top
PC204  0.1U_0603_25V7K  [C_0603]  151.17 33.34 0 top
PC205  10U_0805_6.3V6K  [C_0805]  147.66 33.62 180 top
PC206  10U_0805_6.3V6K  [C_0805]  147.66 31.9 180 top
PC207  1U_0603_10V6K  [C_0603]  154.94 31.02 270 top
PC208  330U_D2_2V_Y  [C_D2]  150.17 52.75 0 bottom
PC209  220U_B2_2.5VM_R15M  [C_B2]  153.53 48.54 180 bottom
PC210  0.033U_0402_16V7K  [C_0402]  146.83 28.48 180 top
PC211  680P_0402_50V7K  [C_0402]  155.51 34.69 90 top
PC212  1U_0603_10V6K  [C_0603]  154.05 25.67 0 top
PC213  0.1U_0402_10V7K  [C_0402]  150.03 25.9 270 top
PC214  0.1U_0402_10V7K  [C_0402]  149.14 25.91 270 top
PC300  0.1U_0402_16V7K  [C_0402]  240.79 27.21 180 bottom
PC301  0.1U_0402_25V6  [C_0402]  252.73 28.98 0 bottom
PC302  2200P_0402_50V7K  [C_0402]  252.73 29.94 0 bottom
PC303  10U_0805_25V6K  [C_0805]  249.68 29.09 90 bottom
PC304  10U_0805_25V6K  [C_0805]  251.46 29.09 90 bottom
PC305  0.1U_0603_25V7K  [C_0603]  247.59 25.81 90 bottom
PC306  220U_B2_2.5VM_R15M  [C_B2]  246.19 21.58 90 bottom
PC307  10U_0805_25V6K  [C_0805]  149.38 106.58 180 top
PC308  1U_0603_6.3V6M  [C_0603]  245.99 30.32 180 bottom
PC309  680P_0402_50V7K  [C_0402]  257.06 28.92 180 bottom
PC310  10U_0805_25V6K  [C_0805]  149.38 106.58 180 bottom
PC311  220U_B2_2.5VM_R15M  [C_B2]  156.34 112.63 180 bottom
PC312  0.1U_0402_16V7K  [C_0402]  130.34 110.03 180 bottom
PC313  1U_0603_6.3V6M  [C_0603]  135.17 112.74 180 bottom
PC314  0.1U_0402_25V6  [C_0402]  148.41 108.93 180 top
PC315  0.1U_0603_25V7K  [C_0603]  136.64 106.77 90 bottom
PC316  2200P_0402_50V7K  [C_0402]  148.41 108.04 180 top
PC317  680P_0402_50V7K  [C_0402]  145.79 106.26 0 top
PC318  220U_B2_2.5VM_R15M  [C_B2]  156.3 115.85 180 bottom
PC405  4.7U_0603_6.3V6K  [C_0603]  207.27 19.08 0 top
PC406  2.2U_0603_16V6K  [C_0603]  206 23.71 90 top
PC408  1U_0402_6.3V6K  [C_0402]  205.68 18.07 270 top
PC409  1U_0402_6.3V6K  [C_0402]  203.9 19.06 90 top
PC500  1000P_0402_50V7K  [C_0402]  140.56 130.4 225 top
PC501  0.22U_0603_16V7K  [C_0603]  101.54 117.06 90 top
PC502  1U_0603_10V6K  [C_0603]  103.63 119.6 0 top
PC503  10U_0805_25V6K  [C_0805]  122.26 128.68 180 bottom
PC504  0.1U_0402_25V6K~D  [C_0402]  121.62 129.58 180 top
PC505  10U_0805_25V6K  [C_0805]  123.7 129.15 0 top
PC506  10U_0805_25V6K  [C_0805]  123.74 128.68 0 bottom
PC507  0.1U_0402_25V6K~D  [C_0402]  121.62 128.69 180 top
PC508  680P_0603_50V7K  [C_0603]  107.76 120.55 0 top
PC509  1U_0603_10V6K  [C_0603]  131.78 126.44 315 bottom
PC510  47P_0402_50V8J  [C_0402]  141.8 128.86 135 bottom
PC511  0.22U_0603_25V7K  [C_0603]  135.94 121.36 225 bottom
PC512  10U_0805_25V6K  [C_0805]  114.96 129.12 0 top
PC513  10U_0805_25V6K  [C_0805]  113.69 128.81 180 bottom
PC514  10U_0805_25V6K  [C_0805]  114.85 128.68 0 bottom
PC515  0.1U_0402_25V6K~D  [C_0402]  113.49 128.67 180 top
PC516  0.1U_0402_25V6K~D  [C_0402]  113.49 129.55 180 top
PC518  1U_0603_10V6K  [C_0603]  137.22 119.38 315 bottom
PC520  470P_0402_50V7K  [C_0402]  142.43 126.13 90 top
PC521  4700P_0402_50V7K~D  [C_0402]  139.31 122.49 225 bottom
PC522  0.22U_0603_16V7K  [C_0603]  131.21 128.79 315 bottom
PC524  680P_0603_50V7K  [C_0603]  115.89 120.36 0 top
PC525  47P_0402_50V8J  [C_0402]  148.13 125.22 180 bottom
PC526  6800P_0402_25V7K~D  [C_0402]  148.13 124.34 180 bottom
PC527  330P_0402_50V7K~D  [C_0402]  138.49 125.69 315 top
PC528  0.15U_0402_10V6K~D  [C_0402]  138.69 120.59 135 bottom
PC529  0.1U_0603_25V7K~D  [C_0603]  137.63 121.6 45 top
PC530  100U_25V_M  [C_ECST250ADA101MF611]  102.15 124.26 315 bottom
PC531  100U_25V_M  [C_ECST250ADA101MF611]  103.69 130.5 225 bottom
PC533  10U_0805_25V6K  [C_0805]  96.58 122.93 135 bottom
PC534  10U_0805_25V6K  [C_0805]  95.32 121.69 135 bottom
PC535  10U_0805_25V6K  [C_0805]  106.66 128.74 0 top
PC536  0.1U_0402_25V6K~D  [C_0402]  107.11 130.96 0 top
PC537  0.1U_0402_25V6K~D  [C_0402]  107.11 130.08 0 top
PC538  0.068U_0603_50V7K  [C_0603]  138.48 120.76 45 top
PC539  0.22U_0402_6.3V6K  [C_0402]  141.14 123.06 135 bottom
PC540  0.22U_0402_6.3V6K  [C_0402]  141.76 123.68 135 bottom
PC541  330P_0402_50V7K  [C_0402]  138.22 128.77 315 top
PC542  0.22U_0603_16V7K  [C_0603]  133.02 122.2 45 bottom
PC543  680P_0603_50V7K  [C_0603]  124.91 120.23 0 top
PC544  0.22U_0402_6.3V6K  [C_0402]  142.36 124.32 135 bottom
PC545  0.082U_0402_16V7K  [C_0402]  142.31 128.95 270 top
PC546  0.01U_0402_50V7K  [C_0402]  140.53 122.45 135 bottom
PC547  .1U_0402_16V7K  [C_0402]  138.5 124.41 135 top
PC600  10U_0805_25V6K  [C_0805]  174.36 37.73 0 top
PC601  10U_0805_25V6K  [C_0805]  183.82 37.67 180 top
PC602  10U_0805_25V6K  [C_0805]  189.09 37.66 0 top
PC603  4.7U 25V K X5R 0805  [C_0805]  174.35 34.25 0 top
PC604  4.7U 25V K X5R 0805  [C_0805]  183.82 34.13 180 top
PC605  4.7U 25V K X5R 0805  [C_0805]  183.82 35.9 180 top
PC606  4.7U 25V K X5R 0805  [C_0805]  174.36 36.01 0 top
PC607  4.7U 25V K X5R 0805  [C_0805]  189.11 35.87 0 top
PC608  4.7U 25V K X5R 0805  [C_0805]  189.14 34.13 0 top
PC609  100U_25V_M  [C_ECST250ADA101MF611]  160.67 42.18 270 bottom
PC612  .1U_0603_25V7K  [C_0603]  178.92 31.18 270 top
PC613  1U_0402_6.3V6K  [C_0402]  181.17 21.95 270 top
PC614  47P_0402_50V8J~D  [C_0402]  174.69 26.46 90 top
PC615  680P_0603_50V7K  [C_0603]  179.34 44.77 90 top
PC616  1500P_0402_50V7K  [C_0402]  176.62 21.71 90 top
PC617  1500P_0402_50V7K  [C_0402]  178.48 21.03 90 top
PC618  47P_0402_50V8J~D  [C_0402]  176.53 27.41 180 top
PC619  .1U_0603_25V7K  [C_0603]  183.59 31.21 270 top
PC621  680P_0603_50V7K  [C_0603]  186.55 46.64 90 top
PC622  1U_0603_6.3V6M  [C_0603]  181.09 29.86 90 top
PC625  .1U_0603_25V7K  [C_0603]  186.64 28.63 90 top
PC626  0.01U_0402_16V7K  [C_0402]  181.66 17.24 0 top
PC627  0.01U_0402_16V7K  [C_0402]  184.63 28.04 0 top
PC628  680P_0603_50V7K  [C_0603]  194.76 45.87 270 top
PC629  .1U_0603_25V7K  [C_0603]  191.36 31.3 180 top
PC634  2200P_0402_50V7K~D  [C_0402]  174.61 32.92 0 top
PC635  2200P_0402_50V7K~D  [C_0402]  184.58 20.79 90 top
PC652  22U_0805_6.3VAM  [C_0805]  135.98 91.23 90 bottom
PC655  22U_0805_6.3VAM  [C_0805]  141.16 91.51 180 bottom
PC656  22U_0805_6.3VAM  [C_0805]  141.16 93.29 180 bottom
PC657  22U_0805_6.3VAM  [C_0805]  141.16 95.06 180 bottom
PC658  22U_0805_6.3VAM  [C_0805]  141.16 96.81 180 bottom
PC659  0.1U_0402_10V7K  [C_0402]  142.83 86.04 180 bottom
PC660  0.1U_0402_10V7K  [C_0402]  138.53 86.07 270 bottom
PC661  22P_0402_50V8J  [C_0402]  140.36 84.22 180 bottom
PC662  680P_0402_50V7K  [C_0402]  145.05 84.15 180 bottom
PC666  22U_0805_6.3VAM  [C_0805]  137.76 91.21 90 bottom
PC701  0.1U_0402_25V6  [C_0402]  33.77 40.53 270 top
PC702  0.047U_0402_25V7K  [C_0402]  42.23 41.61 90 top
PC703  0.1U_0402_25V6  [C_0402]  56.52 33.99 90 top
PC704  2200P_0402_50V7K  [C_0402]  55.63 33.99 90 top
PC705  10U_0805_25V6K  [C_0805]  52.58 33.09 90 top
PC706  10U_0805_25V6K  [C_0805]  54.29 33.09 90 top
PC707  1U_0603_25V6K  [C_0603]  37.72 40.86 270 top
PC708  0.1U_0402_25V6  [C_0402]  38.79 39.32 90 top
PC709  0.1U_0402_25V6  [C_0402]  39.69 41.11 180 top
PC710  2.2U_0603_16V6K  [C_0603]  44.58 41.87 90 top
PC711  1U_0603_25V6K  [C_0603]  40.9 42.19 270 top
PC712  10U_0805_25V5K~D  [C_0805]  70.14 48.92 0 bottom
PC713  10U_0805_25V5K~D  [C_0805]  70.14 47.21 0 bottom
PC714  10U_0805_25V5K~D  [C_0805]  70.17 45.36 0 bottom
PC715  680P_0402_50V7K  [C_0402]  51.17 37.87 0 top
PC716  0.1U_0402_25V6  [C_0402]  49.44 40.01 270 top
PC717  0.1U_0402_25V6  [C_0402]  49.46 38.15 270 top
PC718  100P_0402_50V8J  [C_0402]  40.42 32.91 90 top
PC719  0.1U_0402_25V6  [C_0402]  38.39 35.57 270 top
PC720  100P_0402_50V8J  [C_0402]  41.3 32.92 90 top
PC721  0.1U_0402_25V6  [C_0402]  49.47 36.35 180 top
PC722  1000P_0402_50V7K  [C_0402]  38.8 18.96 270 bottom
PC723  1000P_0402_50V7K  [C_0402]  37.91 18.96 270 bottom
PC724  0.1U_0402_25V6  [C_0402]  60.67 49.16 90 top
PC900  10U_0603_6.3V6M  [C_0603]  108.23 93.97 180 top
PC901  10U_0603_6.3V6M  [C_0603]  112.99 93.98 0 top
PC902  10U_0603_6.3V6M  [C_0603]  100.38 88.48 270 top
PC903  10U_0603_6.3V6M  [C_0603]  109.93 93.97 0 top
PC904  10U_0603_6.3V6M  [C_0603]  176.72 79.02 180 top
PC905  330U_D2_2V_Y  [C_D2]  112.31 107.85 0 bottom
PC906  330U_D2_2V_Y  [C_D2]  103.84 88.48 0 top
PC907  10U_0603_6.3V6M  [C_0603]  170.37 93.18 90 top
PC908  10U_0603_6.3V6M  [C_0603]  176.72 77.22 180 top
PC909  10U_0603_6.3V6M  [C_0603]  171.58 98.95 90 top
PC917  22U_0805_6.3VAM  [C_0805]  113.36 82.24 90 top
PC918  22U_0805_6.3VAM  [C_0805]  115.07 82.24 90 top
PC919  22U_0805_6.3VAM  [C_0805]  116.79 82.24 90 top
PC920  22U_0805_6.3VAM  [C_0805]  118.5 82.24 90 top
PC921  22U_0805_6.3VAM  [C_0805]  119.89 86.77 270 top
PC922  22U_0805_6.3VAM  [C_0805]  119.48 88.23 180 top
PC923  22U_0805_6.3VAM  [C_0805]  119.48 89.95 180 top
PC924  22U_0805_6.3VAM  [C_0805]  108.42 107.53 180 bottom
PC925  22U_0805_6.3VAM  [C_0805]  108.42 109.31 180 bottom
PC926  22U_0805_6.3VAM  [C_0805]  108.42 109.31 180 top
PC927  .1U_0402_16V7K  [C_0402]  178.49 92.2 0 top
PC928  .1U_0402_16V7K  [C_0402]  178.53 95.99 0 top
PC929  .1U_0402_16V7K  [C_0402]  181.31 93.14 180 top
PC930  .1U_0402_16V7K  [C_0402]  184.54 88.3 90 top
PC931  .1U_0402_16V7K  [C_0402]  177.44 91.23 180 top
PC932  .1U_0402_16V7K  [C_0402]  182.62 82.22 0 top
PC933  .1U_0402_16V7K  [C_0402]  189.17 93.72 270 top
PC934  .1U_0402_16V7K  [C_0402]  175.08 95.95 180 top
PC935  22U_0805_6.3VAM  [C_0805]  119.48 91.66 180 top
PC936  22U_0805_6.3VAM  [C_0805]  118.6 93.66 180 top
PC937  22U_0805_6.3VAM  [C_0805]  103.23 109.31 0 top
PC938  22U_0805_6.3VAM  [C_0805]  101.44 109.31 180 top
PC939  22U_0805_6.3VAM  [C_0805]  95.67 109.31 0 top
PC940  22U_0805_6.3VAM  [C_0805]  103.23 107.53 0 bottom
PC941  22U_0805_6.3VAM  [C_0805]  103.23 109.31 0 bottom
PC942  22U_0805_6.3VAM  [C_0805]  101.44 107.6 180 bottom
PC943  22U_0805_6.3VAM  [C_0805]  101.44 109.31 180 bottom
PC944  22U_0805_6.3VAM  [C_0805]  173.76 52.29 180 top
PC945  22U_0805_6.3VAM  [C_0805]  194.55 51.13 270 bottom
PC946  4.7U_0603_6.3V  [C_0603]  171.41 69.74 180 top
PC947  4.7U_0603_6.3V  [C_0603]  183.3 68.11 270 top
PC948  4.7U_0603_6.3V  [C_0603]  171.41 73.55 180 top
PC949  4.7U_0603_6.3V  [C_0603]  171.41 72.32 180 top
PC950  4.7U_0603_6.3V  [C_0603]  170.75 83.28 180 top
PC951  4.7U_0603_6.3V  [C_0603]  185.75 93.49 180 top
PC952  4.7U_0603_6.3V  [C_0603]  182.22 92.28 0 top
PC953  4.7U_0603_6.3V  [C_0603]  174.25 82.47 0 top
PC954  4.7U_0603_6.3V  [C_0603]  174.51 90.41 270 top
PC955  4.7U_0603_6.3V  [C_0603]  174.14 80.28 0 top
PC956  4.7U_0603_6.3V  [C_0603]  185.49 81.07 90 top
PC957  4.7U_0603_6.3V  [C_0603]  181.81 79.08 180 top
PC958  4.7U_0603_6.3V  [C_0603]  175.71 93.27 180 top
PC959  4.7U_0603_6.3V  [C_0603]  179.33 94.34 0 top
PC960  4.7U_0603_6.3V  [C_0603]  177.69 77.22 0 top
PC961  4.7U_0603_6.3V  [C_0603]  171.97 96 90 top
PC962  4.7U_0603_6.3V  [C_0603]  182.41 80.29 0 top
PC963  4.7U_0603_6.3V  [C_0603]  185.86 91.08 180 top
PC964  4.7U_0603_6.3V  [C_0603]  185.68 89.46 270 top
PC965  4.7U_0603_6.3V  [C_0603]  172.54 92.12 90 top
PC966  470U_D2_2VM_R4.5M  [C_D2]  181.25 60.75 180 bottom
PC967  470U_D2_2VM_R4.5M  [C_D2]  176.75 55.84 180 bottom
PC968  470U_D2_2VM_R4.5M  [C_D2]  189.5 51.98 0 top
PC969  470U_D2_2VM_R4.5M  [C_D2]  191.62 57.05 0 bottom
PC970  470U_D2_2VM_R4.5M  [C_D2]  186.72 55.84 180 bottom
PC971  22U_0805_6.3VAM  [C_0805]  95.67 107.6 0 bottom
PC972  22U_0805_6.3VAM  [C_0805]  95.67 109.31 0 bottom
PC973  22U_0805_6.3VAM  [C_0805]  106.79 91.72 0 top
PC974  22U_0805_6.3VAM  [C_0805]  100.63 85.07 270 top
PC975  22U_0805_6.3VAM  [C_0805]  105.12 83.69 180 top
PC976  22U_0805_6.3VAM  [C_0805]  108.22 82.24 90 top
PC977  22U_0805_6.3VAM  [C_0805]  109.93 82.24 90 top
PC978  22U_0805_6.3VAM  [C_0805]  111.65 82.24 90 top
PC979  1U_0402_6.3V6K  [C_0402]  102.7 105.35 0 bottom
PC980  1U_0402_6.3V6K  [C_0402]  102.7 106.21 0 bottom
PC981  1U_0402_6.3V6K  [C_0402]  101.38 105.35 180 bottom
PC982  1U_0402_6.3V6K  [C_0402]  105.84 106.21 180 bottom
PC983  1U_0402_6.3V6K  [C_0402]  101.38 106.21 180 bottom
PC984  1U_0402_6.3V6K  [C_0402]  108.69 105.3 180 bottom
PC985  1U_0402_6.3V6K  [C_0402]  105.84 105.35 180 bottom
PC986  1U_0402_6.3V6K  [C_0402]  108.69 106.21 180 bottom
PC987  1U_0402_6.3V6K  [C_0402]  98.56 105.35 180 bottom
PC988  1U_0402_6.3V6K  [C_0402]  98.56 106.21 180 bottom
PC989  1U_0402_6.3V6K  [C_0402]  95.45 105.35 0 bottom
PC990  1U_0402_6.3V6K  [C_0402]  95.45 106.21 0 bottom
PC991  1U_0402_6.3V6K  [C_0402]  107.01 96.93 180 top
PC992  1U_0402_6.3V6K  [C_0402]  109.36 96.93 180 top
PC993  1U_0402_6.3V6K  [C_0402]  104.6 96.93 180 top
PC994  1U_0402_6.3V6K  [C_0402]  102.25 96.93 180 top
PC995  1U_0402_6.3V6K  [C_0402]  104.81 91.84 0 top
PC996  1U_0402_6.3V6K  [C_0402]  102.9 91.72 0 top
PC997  1U_0402_6.3V6K  [C_0402]  101.13 91.59 0 top
PC998  1U_0402_6.3V6K  [C_0402]  100.21 91.19 270 top
PC999  .1U_0402_16V7K  [C_0402]  185.49 85.28 270 top
PC1000  .1U_0402_16V7K  [C_0402]  178.48 90.34 0 top
PC1001  .1U_0402_16V7K  [C_0402]  173.5 77.23 0 top
PC1002  .1U_0402_16V7K  [C_0402]  186.26 95.9 0 top
PC1003  .1U_0402_16V7K  [C_0402]  177.44 89.26 180 top
PC1004  .1U_0402_16V7K  [C_0402]  178.37 82.48 0 top
PC1005  .1U_0402_16V7K  [C_0402]  182.64 90.38 0 top
PC1006  .1U_0402_16V7K  [C_0402]  182.62 84.04 0 top
PC1007  .1U_0402_16V7K  [C_0402]  174.51 86.33 90 top
PC1008  .1U_0402_16V7K  [C_0402]  177.48 83.36 180 top
PC1009  22U_0805_6.3VAM  [C_0805]  168.91 53.77 180 top
PC1010  22U_0805_6.3VAM  [C_0805]  170.92 66.17 90 top
PC1011  22U_0805_6.3VAM  [C_0805]  173.76 50.57 180 top
PC1012  22U_0805_6.3VAM  [C_0805]  170.65 97.12 180 top
PC1013  22U_0805_6.3VAM  [C_0805]  174.92 50.57 0 top
PC1014  22U_0805_6.3VAM  [C_0805]  196.19 60.4 0 bottom
PC1015  22U_0805_6.3VAM  [C_0805]  170.8 52.05 180 top
PC1016  22U_0805_6.3VAM  [C_0805]  174.92 52.29 0 top
PC1017  22U_0805_6.3VAM  [C_0805]  186.84 50.69 180 top
PD1  SM24_SOT23  [TP0610K-T1-E3_SOT23-3]  279.31 33.04 0 top
PD2  -  [TVNST52302AB0_SOT523-3]  72.36 29.63 270 top
PD3  -  [TVNST52302AB0_SOT523-3]  72.37 25.26 270 top
PD5  -  [BAS40CW_SOT323-3]  257.93 15.74 90 bottom
PD100  -  [BAS40CW_SOT323-3]  24.2 38.33 270 top
PD101  -  [LL4148_LL34-2]  20.13 39.24 270 top
PD700  -  [BAT54CW_SOT323-3]  33.88 38 270 top
PH1  100K_0402_1%_TSM0B104F4251RZ  [R_0402]  123.83 92.05 270 top
PH500  470K_0402_5%_ TSM0B474J4702RE  [R_0402]  123.71 121.88 180 top
PH501  10K_0402_5%_ERTJ0ER103J  [R_0402]  129.61 114.66 270 bottom
PJP100  -  [JUMP_43X118]  29.72 38.15 90 bottom
PJP102  -  [JUMP_43X118]  28.03 19.39 0 bottom
PJP200  -  [JUMP_43X118]  150.56 47.6 180 bottom
PJP202  -  [JUMP_43X39]  147.08 35.65 180 top
PJP203  -  [JUMP_43X39]  148.85 44.34 270 top
PJP300  -  [JUMP_43X118]  243.16 20.55 180 bottom
PJP301  -  [JUMP_43X39]  247.61 29.2 90 bottom
PJP302  -  [JUMP_43X118]  156.11 108.38 0 bottom
PJP303  -  [JUMP_43X39]  149 104.61 180 top
PJP304  -  [JUMP_43X39]  155.54 104.63 0 bottom
PJP305  -  [JUMP_43X39]  155.56 102.33 0 bottom
PJP403  -  [JUMP_43X39]  207.72 23.33 90 top
PJP600  -  [JUMP_43X118]  166.62 48.48 0 top
PJP901  -  [JUMP_43X118]  143.53 95.54 0 bottom
PJP902  -  [JUMP_43X79]  137.04 89.15 270 bottom
PJPDC1  ACES_50293-0117N-001  [ACES_50293-0117N-001_11P]  56.2 16.58 90 bottom
PL1  SMB3025500YA_2P  [CHENG_SMB3025500YA_2P]  50.52 24.79 180 bottom
PL2  BLM15HG601SN1D_2P  [MURAT_BLM15HG601SN1D_2P]  280.28 37 180 top
PL3  SMB3025500YA_2P  [CHENG_SMB3025500YA_2P]  50.8 21.17 180 bottom
PL4  SMB3025500YA_2P  [CHENG_SMB3025500YA_2P]  70.54 38.89 180 bottom
PL5  SMB3025500YA_2P  [CHENG_SMB3025500YA_2P]  70.55 42.55 180 bottom
PL100  1UH_6.6A_20%_5X5X3_M  [L_5X5X3_M_2P]  43.96 28.98 180 bottom
PL101  S COIL 2.2UH +-20% 7.8A 7X7X3  [CYNTE_PCMC063T-3R3MN_2P]  27.97 25.81 0 bottom
PL102  S COIL 2.2UH +-20% 7.8A 7X7X3  [CYNTE_PCMC063T-3R3MN_2P]  34.52 33.3 180 bottom
PL201  1UH_11A_20%_7X7X3_M  [L_7X7X3_M_2P]  152.72 42.89 270 bottom
PL300  1UH_6.6A_20%_5X5X3_M  [L_5X5X3_M_2P]  253.95 20.78 180 bottom
PL301  1UH_PCMB104T-1R0MH_18A_20%  [L_10X10X4_M_2P]  139.51 112.61 0 bottom
PL501  0.22UH 20% MMD-06DZNR22MEO1L 25A  [PANAS_ETQP4LR15AFM_4P]  109.92 112.12 90 bottom
PL502  0.22UH 20% MMD-06DZNR22MEO1L 25A  [PANAS_ETQP4LR15AFM_4P]  117.48 112.12 90 bottom
PL503  0.22UH 20% MMD-06DZNR22MEO1L 25A  [PANAS_ETQP4LR15AFM_4P]  125.03 111.99 90 bottom
PL504  FBMA-L11-453215-800LMA90T_1812  [L_1812-1806]  87.16 109.95 180 bottom
PL601  S COIL 0.22UH 20% MMD-06DZNR22MEO1L 25A  [CYNTE_PCME064T-R22MS0R985_2P]  175.14 51.47 270 bottom
PL602  S COIL 0.22UH 20% MMD-06DZNR22MEO1L 25A  [CYNTE_PCME064T-R22MS0R985_2P]  182.37 51.47 270 bottom
PL603  S COIL 0.22UH 20% MMD-06DZNR22MEO1L 25A  [CYNTE_PCME064T-R22MS0R985_2P]  189.69 51.5 270 bottom
PL605  1UH_1239AS-H-1R0M-P2_3A_20%  [TOKO_1239AS-H-1R0M-P2_2P]  144.82 91.62 180 bottom
PL700  5.6UH_PCMB104T-5R6MS_8A_20%  [CYNTE_PCMB104T-5R6MS_2P]  52.07 40.43 0 bottom
PL701  1UH_6.6A_20%_5X5X3_M  [L_5X5X3_M_2P]  49.71 28.51 90 bottom
PQ2  MMST3904-7-F_SOT323~D  [RHU002N06_SOT323-3]  284.73 32.55 90 top
PQ3  -  [SI3457CDV-T1-GE3_TSOP6]  67.23 14.65 90 top
PQ4  2N7002KW_SOT323-3  [SSM3K7002FU_SC70-3]  68.9 17.15 270 top
PQ7  FDV301N_G 1N SOT23-3  [FDV301N_NL_SOT23-3]  283.8 35.87 270 top
PQ8  2N7002KW_SOT323-3  [SSM3K7002FU_SC70-3]  71.42 20.27 0 top
PQ100  MDV1525URH 1N PDFN33-8  [SI7326DN-T1-E3_PAK1212-8]  34.95 23.48 0 top
PQ101  MDU1512RH 1N POWERDFN56-8  [SI7170DP-T1-GE3_POWERPAK8-5]  32.7 25.56 180 top
PQ102  MDV1525URH 1N PDFN33-8  [SI7326DN-T1-E3_PAK1212-8]  35.28 33.06 270 top
PQ103  MDU1512RH 1N POWERDFN56-8  [SI7170DP-T1-GE3_POWERPAK8-5]  29.78 30.44 0 top
PQ200  MDV1528URH 1N PDFN33-8  [AON7520_DFN8-5]  149.2 37.71 90 top
PQ201  MDV1526URH 1N PDFN33-8  [AON7520_DFN8-5]  152.95 40.39 180 top
PQ300  MDV1528URH 1N PDFN33-8  [AON7520_DFN8-5]  251.05 24.79 180 bottom
PQ301  MDV1526URH 1N PDFN33-8  [AON7520_DFN8-5]  252.82 26.8 0 bottom
PQ302  -  [MDU1511RH_POWERDFN56-8-5]  141.61 114.58 180 top
PQ303  -  [MDU1516URH_POWERDFN56-8-5]  144.02 114.26 270 top
PQ501  -  [AON6970_DFN5X6D-8-7]  122.14 123.22 90 bottom
PQ502  -  [AON6970_DFN5X6D-8-7]  122.14 127.03 270 top
PQ503  -  [AON6970_DFN5X6D-8-7]  113.63 127.03 270 top
PQ504  -  [AON6970_DFN5X6D-8-7]  113.63 123.22 90 bottom
PQ505  -  [AON6970_DFN5X6D-8-7]  105.24 127.03 270 top
PQ506  -  [AON6970_DFN5X6D-8-7]  105.24 123.22 90 bottom
PQ605  -  [AON6970_DFN5X6D-8-7]  171.38 43.23 270 top
PQ606  -  [AON6970_DFN5X6D-8-7]  171.38 38.81 90 bottom
PQ607  -  [AON6970_DFN5X6D-8-7]  185.49 42.66 270 bottom
PQ608  -  [AON6970_DFN5X6D-8-7]  185.49 39.46 90 top
PQ609  -  [AON6970_DFN5X6D-8-7]  187.48 38.83 90 bottom
PQ610  2N7002KW_SOT323-3  [SSM3K7002FU_SC70-3]  178.45 18.14 270 top
PQ611  -  [AON6970_DFN5X6D-8-7]  187.39 43.21 270 top
PQ700  2N7002KW_SOT323-3  [SSM3K7002FU_SC70-3]  29.68 38.08 90 top
PQ701  -  [MDU1516URH_POWERDFN56-8-5]  36.26 16.09 180 bottom
PQ702  -  [MDU1516URH_POWERDFN56-8-5]  39.31 20.6 0 top
PQ703  -  [MDU1516URH_POWERDFN56-8-5]  71.5 50.77 180 bottom
PQ704  -  [MDU1516URH_POWERDFN56-8-5]  61.79 38.95 180 top
PQ705  2N7002W-T/R7_SOT323-3  [SSM3K7002FU_SC70-3]  47.81 41.81 90 top
PQ706  MDV1525URH 1N  [SI7326DN-T1-E3_PAK1212-8]  54.14 36.15 0 top
PQ707  -  [MDU1516URH_POWERDFN56-8-5]  44.07 16.66 180 bottom
PQ710  S TR 2N7002KDW 2N SOT-363-6  [2N7002DW-7-F_SOT363-6]  62.11 49.81 270 top
PR2  1K_0402_1%  [R_0402]  261.05 15.85 270 bottom
PR3  2.2K_0402_5%  [R_0402]  287.65 35.49 270 top
PR4  33_0402_5%  [R_0402]  287.65 37.33 270 top
PR6  100K_0402_1%  [R_0402]  282.01 34.61 90 top
PR8  10K_0402_1%  [R_0402]  286.01 32.32 90 top
PR9  15K_0402_1%  [R_0402]  282.01 32.83 90 top
PR12  100K_0402_1%  [R_0402]  65.23 19.15 0 top
PR13  100K_0402_1%  [R_0402]  68.25 19.15 180 top
PR14  100K_0402_1%  [R_0402]  69.95 14.06 0 top
PR15  100_0402_5%  [R_0402]  71.09 26.87 90 top
PR16  10K_0402_1%  [R_0402]  72.51 27.79 270 top
PR17  0_0402_5%  [R_0402]  69.01 14.08 90 top
PR18  100_0402_5%  [R_0402]  44.88 32.88 90 top
PR19  100_0402_5%  [R_0402]  69.6 29.9 90 top
PR20  100_0402_5%  [R_0402]  44.5 31.57 180 top
PR21  100_0402_5%  [R_0402]  69.6 28.15 90 top
PR22  100_0402_5%  [R_0402]  69.6 26.39 90 top
PR23  110K_0402_1%  [R_0402]  293.19 13.97 270 top
PR24  12.1K_0402_1%  [R_0402]  299.56 23.27 90 top
PR25  12.1K_0402_1%  [R_0402]  298.48 23.27 90 top
PR26  100K_0402_1%  [R_0402]  295.07 13.06 90 top
PR28  100K_0402_1%  [R_0402]  71.23 23.42 0 top
PR100  0_0402_5%  [R_0402]  24.99 35.57 90 top
PR101  6.49K_0402_1%  [R_0402]  19.57 26.96 90 top
PR102  15.4K_0402_1%  [R_0402]  19.94 32.15 90 top
PR103  10K_0402_1%  [R_0402]  20.46 26.96 90 top
PR104  10.2K_0402_1%  [R_0402]  20.58 30.11 90 top
PR105  8.87K_0402_1%  [R_0402]  19.59 26.08 0 top
PR106  7.5K_0402_1%  [R_0402]  20.96 33.06 270 top
PR107  200_0402_1%  [R_0402]  22.29 32.15 90 top
PR108  0_0603_5%  [R_0603]  24.64 24.22 90 top
PR109  0_0603_5%  [R_0603]  24.39 32.16 90 top
PR110  4.7_1206_5%  [R_1206]  34.55 21.81 270 top
PR111  4.7_1206_5%  [R_1206]  27.94 36.03 270 top
PR112  0_0402_5%  [R_0402]  24.07 35.57 90 top
PR113  2.2K_0402_5%  [R_0402]  22.86 39.47 270 top
PR114  0_0402_5%  [R_0402]  25.94 35.57 90 top
PR115  1M_0402_1%  [R_0402]  21.97 39.47 270 top
PR116  200K_0402_1%  [R_0402]  22.62 37.68 180 top
PR200  2.2_0603_5%  [R_0603]  150.15 33.34 180 top
PR201  16.2K_0402_1%  [R_0402]  155.11 32.01 180 top
PR202  4.7_1206_5%  [R_1206]  151.7 35.21 0 top
PR203  5.1_0603_5%  [R_0603]  155.45 26.95 180 top
PR204  2.2_0603_5%  [R_0603]  155.45 28.22 180 top
PR205  8.06K_0402_1%  [R_0402]  147.74 27.23 90 top
PR206  887K_0402_1%  [R_0402]  151.81 24.98 90 top
PR207  10K_0402_1%  [R_0402]  146.83 27.27 180 top
